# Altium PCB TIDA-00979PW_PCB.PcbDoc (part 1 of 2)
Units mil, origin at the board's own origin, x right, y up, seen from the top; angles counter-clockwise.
Board outline 2100 x 2800 mil, 4 copper layers (Top Layer, L02 - GND, L03 - SUPPLY, Bottom Layer), stack 61.17 mil thick; 75 components, 60 nets, 300 pads, 112 vias.
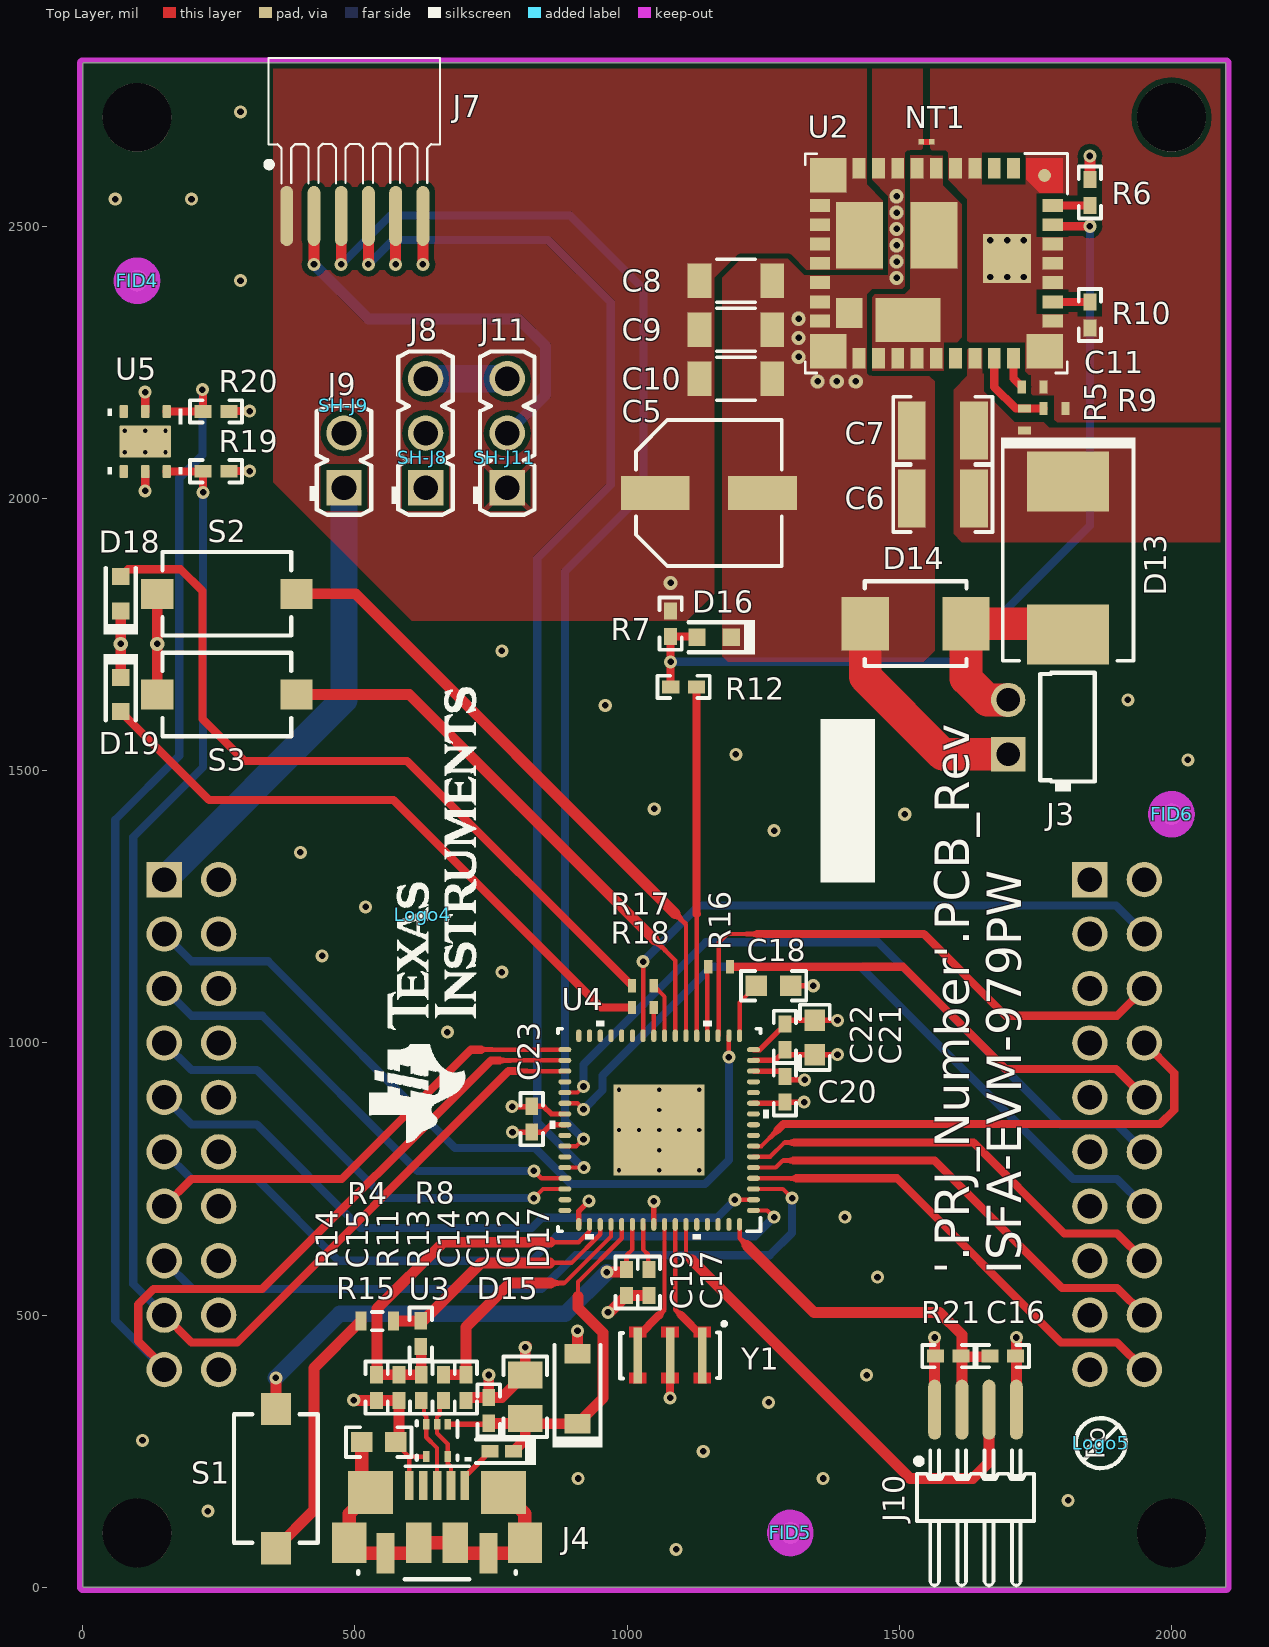
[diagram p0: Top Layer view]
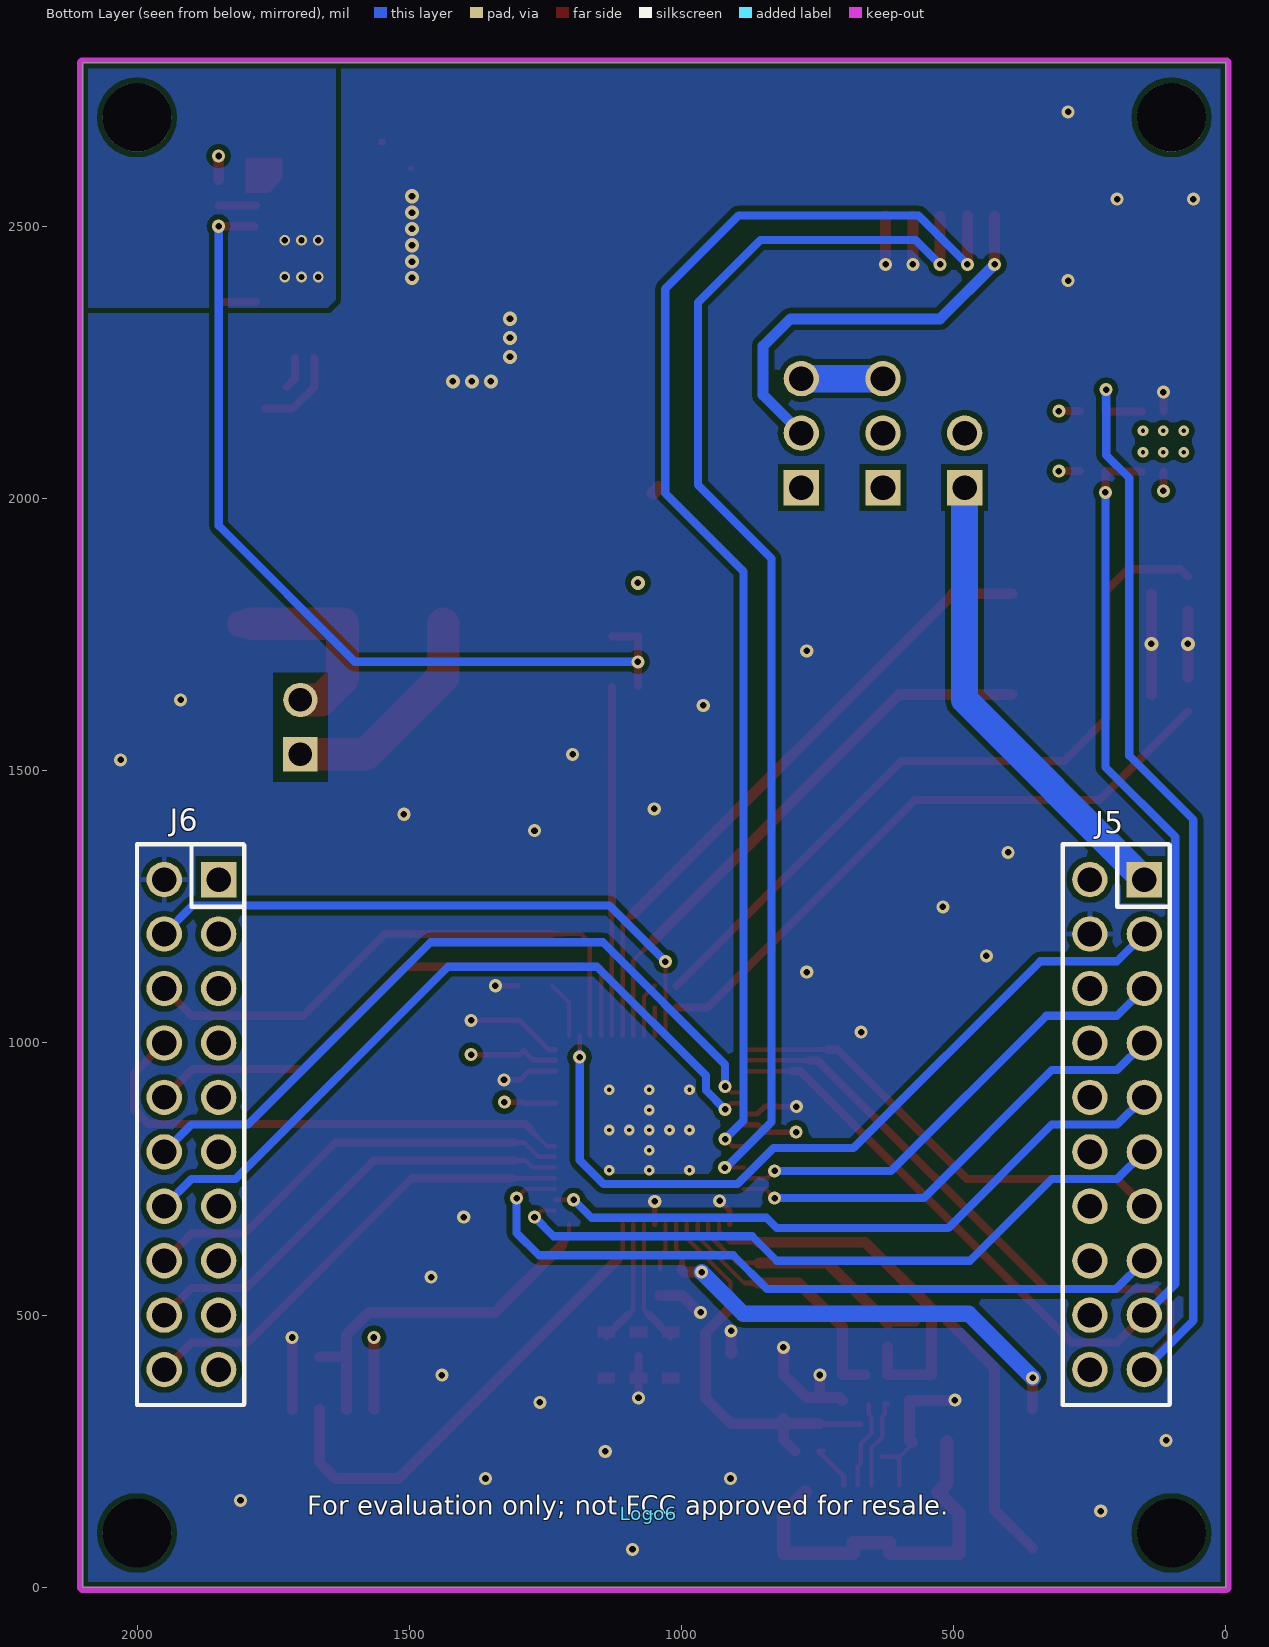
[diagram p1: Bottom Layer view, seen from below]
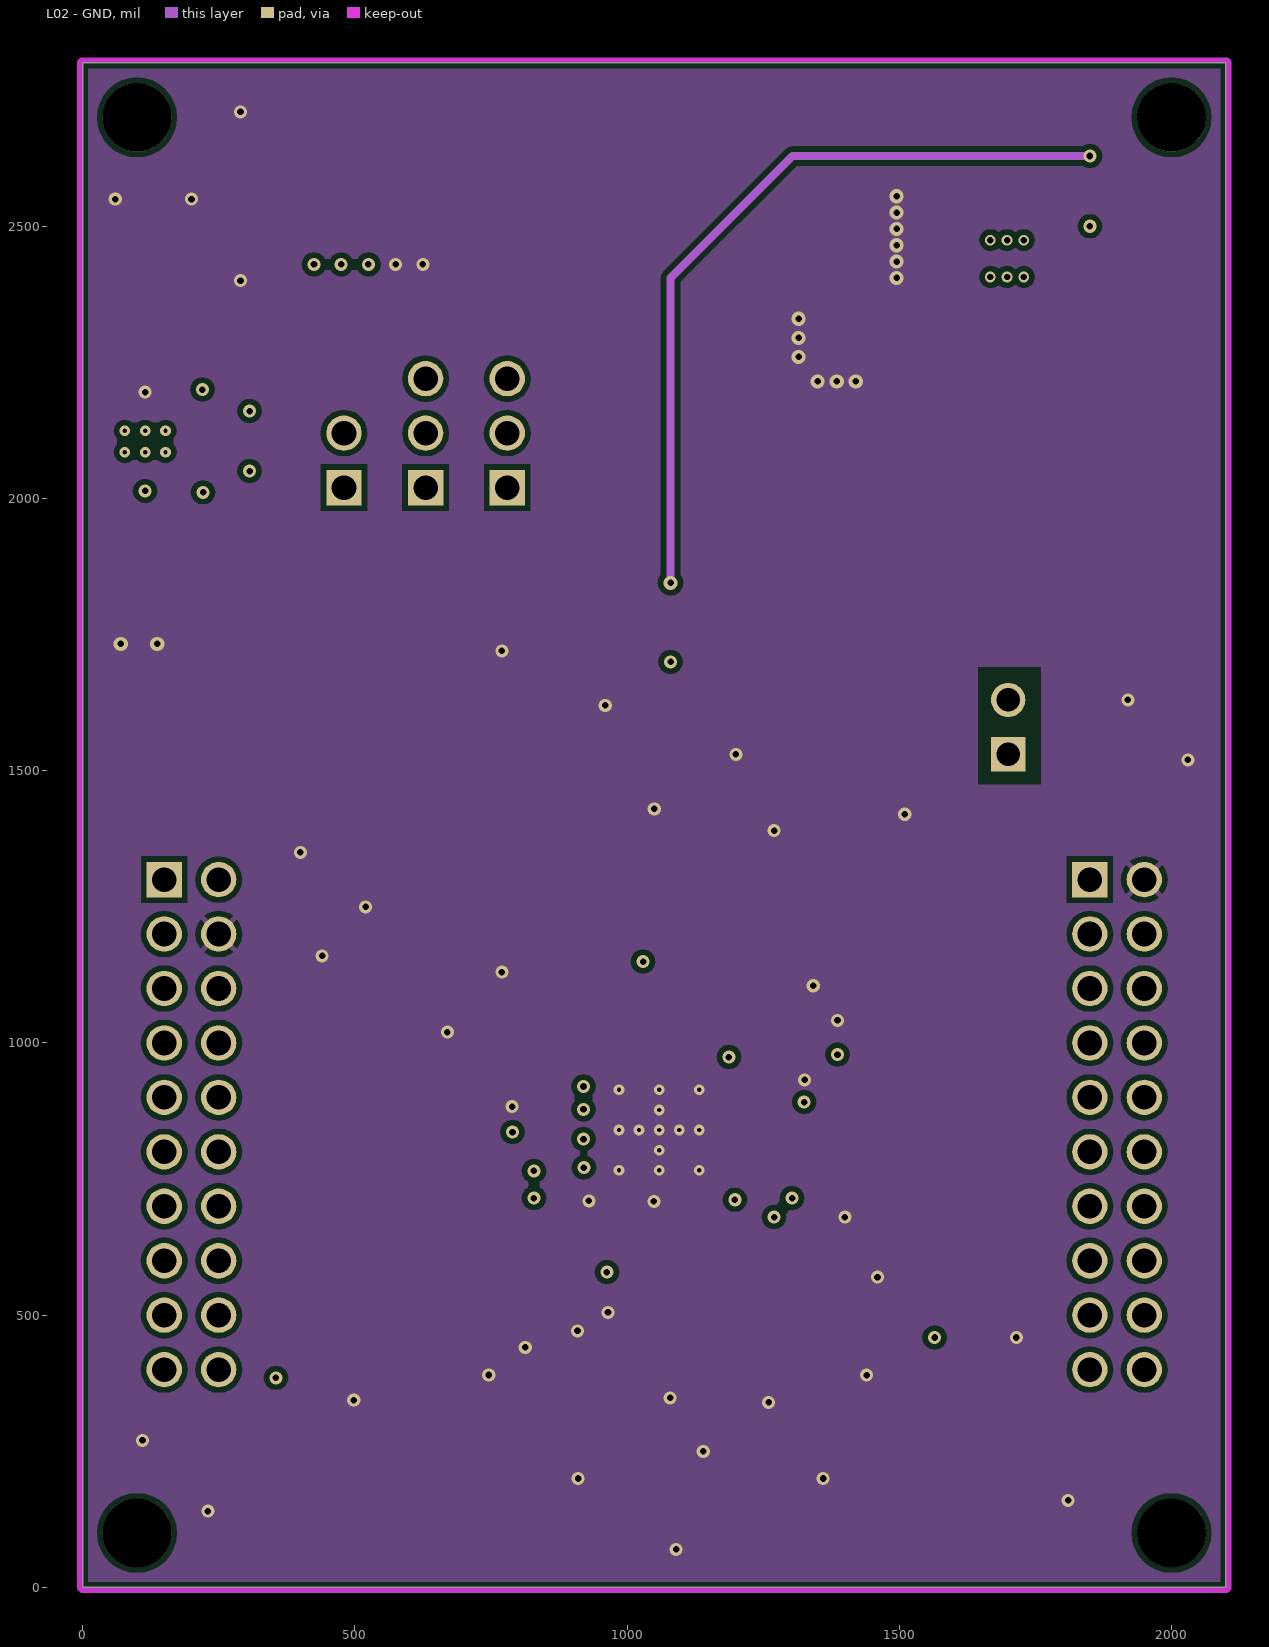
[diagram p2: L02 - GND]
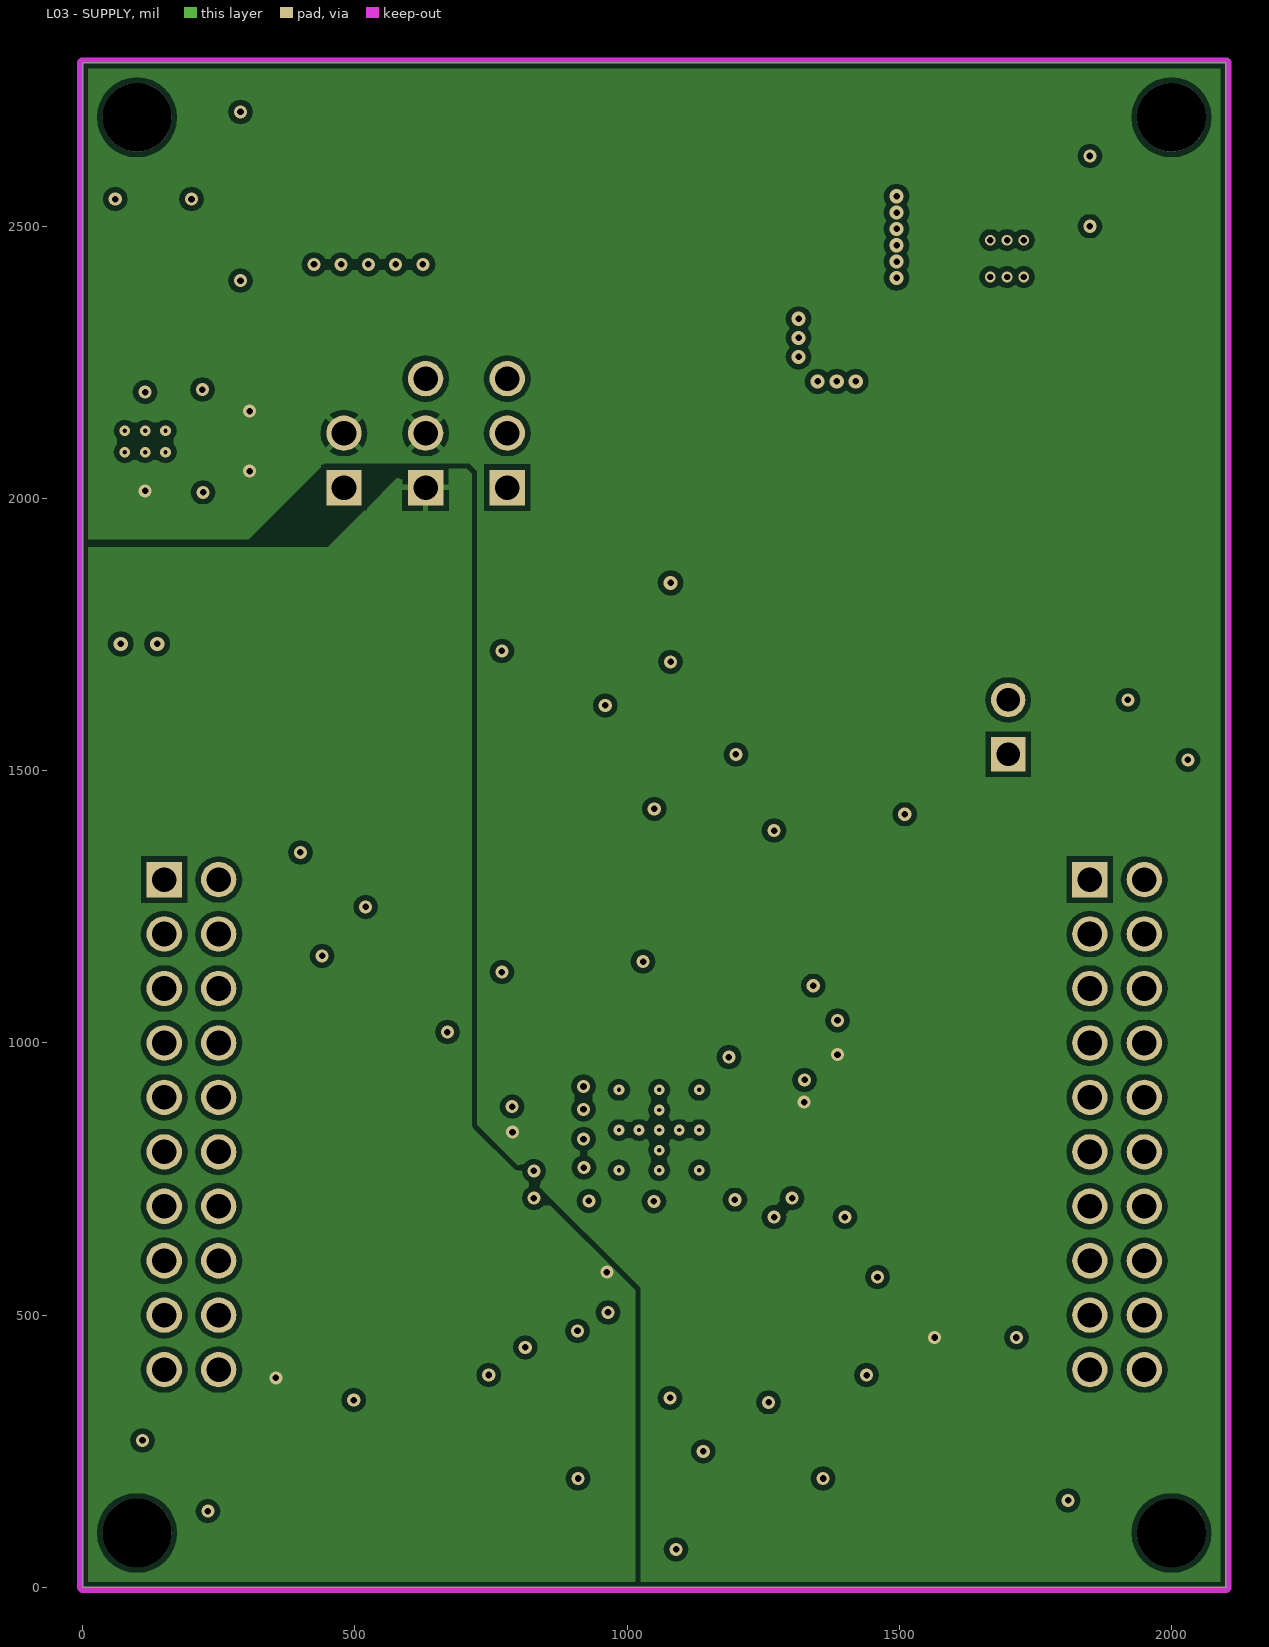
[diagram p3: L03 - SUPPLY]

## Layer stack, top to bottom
Top Solder: solder mask 0.4, Solder Resist, Dk 3.5
Top Layer: signal copper 1.4
Dielectric1: core 10, FR-4, Dk 4.8
L02 - GND: signal copper 1.4
Dielectric 3: prepreg 35.57, FR-4, Dk 4.8
L03 - SUPPLY: signal copper 1.4
Dielectric 2: core 10, FR-4, Dk 4.8
Bottom Layer: signal copper 1.4
Bottom Solder: solder mask 0.4, Solder Resist, Dk 3.5

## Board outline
0,0 2100,0 2100,2800 0,2800

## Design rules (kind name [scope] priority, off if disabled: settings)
AcuteAngle [All] p1: minimum=4.50000000000000E+0001 checktracksonly=FALSE
AssemblyTestPointUsage [All] p1: valid=2
Clearance Clearance_Region_NT1 [All vs InComponent('NT1')] p1: gap=7.87 except(0: Poly-Region)
Clearance Clearance_Keepouts [((IsTrack Or IsArc) And Not InPoly) And IsFree and IsKeepOut vs ((IsTrack Or IsArc) And Not InPoly) And IsFree and IsKeepOut] p2: gap=0
Clearance Clearance_Poly [InPolygon] p3: gap=10
Clearance [All] p4: gap=7.87
ComponentClearance ComponentClearance_MountingHoles_FiducialMarks [InComponentClass('Mounting Holes') vs InComponentClass('FiducialMark')] p1: gap=50 collisioncheckmode=3 verticalgap=10 showdistances=FALSE
ComponentClearance ComponentClearance_Shunt [InComponentClass('Header') vs HasFootprint('Wurth_60900213421')] p2: gap=0 collisioncheckmode=3 verticalgap=0 showdistances=FALSE
ComponentClearance ComponentClearance_Logo [InComponentClass('Logo')] p3: gap=50 collisioncheckmode=3 verticalgap=10 showdistances=FALSE
ComponentClearance ComponentClearance_ScrewToNut [(HasFootprint('NY PMS 440 0025 PH')) vs (HasFootprint('Keystone_1902C'))] p4: gap=5 collisioncheckmode=3 verticalgap=10 showdistances=FALSE
ComponentClearance ComponentClearance_MountingHoles [InComponentClass('Mounting Holes')] p5: gap=250 collisioncheckmode=3 verticalgap=100000 showdistances=FALSE
ComponentClearance ComponentClearance_SmallPassives [HasFootprint('0201*') or HasFootprint('0402*') or HasFootprint('0508') or HasFootprint('0603*') or HasFootprint('0612') or HasFootprint('0805*') or HasFootprint('0815*') or HasFootprint('0830*') or HasFootprint('1206*') or HasFootprint('1210*') or HasFootprint('1808*') or HasFootprint('1812*') or HasFootprint('1825*') or HasFootprint('2010*') or HasFootprint('2220*') or HasFootprint('2225*') or HasFootprint('2512*') or HasFootprint('2728*') or HasFootprint('3518*') vs HasFootprint('0201*') or HasFootprint('0402*') or HasFootprint('0508') or HasFootprint('0603*') or HasFootprint('0612') or HasFootprint('0805*') or HasFootprint('0815*') or HasFootprint('0830*') or HasFootprint('1206*') or HasFootprint('1210*') or HasFootprint('1808*') or HasFootprint('1812*') or HasFootprint('1825*') or HasFootprint('2010*') or HasFootprint('2220*') or HasFootprint('2225*') or HasFootprint('2512*') or HasFootprint('2728*') or HasFootprint('3518*')] p6: gap=14.96 collisioncheckmode=3 verticalgap=10 showdistances=FALSE
ComponentClearance ComponentClearance_THtoSMT [IsThruComponent vs IsSMTComponent] p7: gap=40 collisioncheckmode=3 verticalgap=30 showdistances=FALSE
ComponentClearance ComponentClearance_THtoTH [IsThruComponent vs IsThruComponent] p8: gap=30 collisioncheckmode=3 verticalgap=30 showdistances=FALSE
ComponentClearance [All] p9: gap=30 collisioncheckmode=3 verticalgap=10 showdistances=FALSE
ComponentClearance ComponentClearance_SHUNT2 [HasFootprint('Wurth_60900213421')] p10: gap=30 collisioncheckmode=3 verticalgap=10 showdistances=TRUE
DiffPairsRouting [All] p1: maxlimit=100 minlimit=10 mostfreqgap=10 toplayer_minwidth=15 toplayer_maxwidth=15 toplayer_prefwidth=15 midlayer1_minwidth=15 midlayer1_maxwidth=15 midlayer1_prefwidth=15 midlayer2_minwidth=15 midlayer2_maxwidth=15 midlayer2_prefwidth=15 bottomlayer_minwidth=15 bottomlayer_maxwidth=15 bottomlayer_prefwidth=15 maxuncoupledlength=1000
FabricationTestPointUsage TestPointUsage [All] p1: valid=2 allowmultiple=FALSE
FabricationTestpoint Testpoint [All] p1: side=3 testpointundercomponent=TRUE minsize=40 maxsize=100 preferedsize=60 minholesize=0 maxholesize=40 preferedholesize=32 testpointgrid=1 allowsidetop=TRUE allowsidebottom=TRUE usegrid=TRUE gridtolerance=0.01
FanoutControl Fanout_LCC [IsLCC] p1: bgadir=Out bgaviamode=Centered fanoutstyle=Auto fanoutdirection=Alternating viagrid=1 // Fanout_LCC (Default Rule)
FanoutControl Fanout_BGA [IsBGA] p2: bgadir=Out bgaviamode=Centered fanoutstyle=Auto fanoutdirection=Alternating viagrid=1 // Fanout_BGA (Default Rule)
FanoutControl Fanout_Default [All] p4: bgadir=Out bgaviamode=Centered fanoutstyle=Auto fanoutdirection=Alternating viagrid=1 // Fanout_Default (Default Rule)
FanoutControl Fanout_Small [(CompPinCount < 5)] p5: bgadir=Out bgaviamode=Centered fanoutstyle=Auto fanoutdirection=OutThenIn viagrid=1 // Fanout_Small (Default Rule)
HoleSize [All] p1: absolutevalues=TRUE maxlimit=251 minlimit=7.87 maxpercent=80.000 minpercent=20.000
MinimumAnnularRing MinimumAnnularRing_ThermalPadVias [IsVia and InAnyComponent] p1: minimumring=3.94
MinimumAnnularRing [All] p2: minimumring=6
MinimumSolderMaskSliver MinimumSolderMaskSliver_Logo [InComponentClass('Logo') vs InComponentClass('Logo')] p1: minsoldermaskwidth=0.7
MinimumSolderMaskSliver [All] p2: minsoldermaskwidth=3.94
PlaneConnect [All] p1: planeconnectstyle=Direct reliefexpansion=10 reliefentries=4 reliefconductorwidth=10 reliefairgap=10
PolygonConnect PolygonConnect_9 [IsThruPin vs IsNamedPolygon('GND_L04_P018')] p1: connectstyle=Relief reliefconductorwidth=10 reliefentries=4 polygonreliefangle="90 Angle" airgapwidth=10
PolygonConnect PolygonConnect_8 [IsThruPin vs IsNamedPolygon('+3V3_L03_P012')] p2: connectstyle=Relief reliefconductorwidth=10 reliefentries=4 polygonreliefangle="45 Angle" airgapwidth=10
PolygonConnect PolygonConnect_7 [IsThruPin vs IsNamedPolygon('VUSB_L03_P014')] p3: connectstyle=Relief reliefconductorwidth=10 reliefentries=4 polygonreliefangle="90 Angle" airgapwidth=10
PolygonConnect PolygonConnect_6 [IsThruPin vs IsNamedPolygon('GND_L02_P010')] p4: connectstyle=Relief reliefconductorwidth=10 reliefentries=4 polygonreliefangle="45 Angle" airgapwidth=10
PolygonConnect PolygonConnect_5 [IsThruPin vs IsNamedPolygon('VLED_L01_P008')] p5: connectstyle=Relief reliefconductorwidth=10 reliefentries=4 polygonreliefangle="45 Angle" airgapwidth=10
PolygonConnect PolygonConnect_4 [IsThruPin vs IsNamedPolygon('GND_L01_P006')] p6: connectstyle=Relief reliefconductorwidth=10 reliefentries=4 polygonreliefangle="45 Angle" airgapwidth=10
PolygonConnect PolygonConnect_3 [IsThruPin vs IsNamedPolygon('NETC6_1_L01_P004')] p7: connectstyle=Relief reliefconductorwidth=10 reliefentries=4 polygonreliefangle="45 Angle" airgapwidth=10
PolygonConnect PolygonConnect_2 [IsThruPin vs IsNamedPolygon('NETU2_6_L01_P002')] p8: connectstyle=Relief reliefconductorwidth=10 reliefentries=4 polygonreliefangle="45 Angle" airgapwidth=10
PolygonConnect PolygonConnect_1 [IsThruPin vs IsNamedPolygon('AGND_L01_P000')] p9: connectstyle=Relief reliefconductorwidth=10 reliefentries=4 polygonreliefangle="45 Angle" airgapwidth=10
PolygonConnect [All] p10: connectstyle=Direct reliefconductorwidth=10 reliefentries=4 polygonreliefangle="90 Angle" airgapwidth=10
RoutingVias ThermalPadVias [IsVia and InAnyComponent] p1: holewidth=7.87 width=19.68 viastyle="Through Hole" minholewidth=7.87 minwidth=19.68 maxholewidth=12.99 maxwidth=23.62
RoutingVias [All] p2: holewidth=12 width=26 viastyle="Through Hole" minholewidth=7.87 minwidth=19 maxholewidth=40 maxwidth=65
ShortCircuit ShortCircuit_HDC1080 [HasFootprintPad('DMB0006A','7') vs IsVia] p1: allowed=TRUE
ShortCircuit [All] p2: allowed=FALSE
SilkToBoardRegionClearance [Not ((IsComment or IsDesignator) And (Hide <> 'False')) and not InRegion(1000,500,4000,800)] p1:
SilkToSilkClearance SilkToSilkClearance_Pb-FreeLogo [(HasFootprint('Pb-Free_Overlay_Medium') OR HasFootprint('Pb-Free_Overlay_Small')) vs (HasFootprint('Pb-Free_Overlay_Medium') OR HasFootprint('Pb-Free_Overlay_Small'))] p1: silktosilkclearance=0
SilkToSilkClearance [All] p2: silktosilkclearance=4
SilkToSolderMaskClearance SilkToComponentPadClearance [IsPad and InAnycomponent] p1: minsilkscreentomaskgap=5 clearancetoexposedcopper=TRUE
SilkToSolderMaskClearance "Silk to Solder Mask Opening" [All] p2: minsilkscreentomaskgap=4 clearancetoexposedcopper=FALSE
SolderMaskExpansion [All] p1: expansion=1.97
Width [All] p1: maxlimit=100 minlimit=6 preferedwidth=15 checkconnectedcopper=TRUE
14 further rules are at their usual default settings.

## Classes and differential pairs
component class Header: J3 J8 J9 J11
component class AssemblyNote: ZZ5 ZZ6 ZZ7
component class FiducialMark: FID4 FID5 FID6
component class TIDA-00979PW_CoverSheet: FID4 FID5 FID6 Logo4 Logo5 Logo6 ZZ4 ZZ5 ZZ6 ZZ7
component class Logo: Logo4
component class TIDA-00979PW_Control: C5 C6 C7 C8 C9 C10 C11 C12 C13 C14 C15 C16 C17 C18 C19 C20 C21 C22 C23 D1 D13 D14 D15 D16 D17 D18 D19 J3 J4 J5 J6 J7 J8 J9 J10 J11 J? NT1 R4 R5 R6 R7 R8 R9 R10 R11 R12 R13 R14 R15 R16 R17 R18 R19 R20 R21 S1 S2 S3 SH-J8 SH-J9 SH-J11 U2 U3 U4 U5 Y1

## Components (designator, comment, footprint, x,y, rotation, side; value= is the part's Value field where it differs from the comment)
C5 "EEE-FK1E680P" SM_RADIAL_D 1150.32,2010 r0 top
C6 "C3225X7S2A335M200AB" 1210 1580,2000 r180 top
C7 "C3225X7S2A335M200AB" 1210 1580,2125 r180 top
C8 "C3216X5R1E476M160AC" 1206_190 1200,2400 r0 top
C9 "C3216X5R1E476M160AC" 1206_190 1200,2310 r0 top
C10 "C3216X5R1E476M160AC" 1206_190 1200,2220 r0 top
C11 "C1005X7R1E223K" 0402S 1745,2205 r0 top
C12 "GRM21BR71C475KA73L" 0805_HV 813,350 r90 top
C13 "C1005X7R1H104K050BB" 0402 746,325 r90 top
C14 "500R07S100JV4T" 0402 704,367 r270 top
C15 "500R07S100JV4T" 0402 581,367 r270 top
C16 "885012205008" 0402 1690,425 r0 top
C17 "C1005X7R1C224K050BC" 0402 1040,560 r270 top
C18 "C0603C474K8RACTU" 0603 1269,1105 r0 top
C19 "C1005X7R1C224K050BC" 0402 999,560 r270 top
C20 "C1005X7R1H104K050BB" 0402 1290,915 r90 top
C21 "C1608X5R1A106M080AC" 0603 1345,1010 r90 top
C22 "C1005X7R1H104K050BB" 0402 1290,1011 r90 top
C23 "C1005X7R1H104K050BB" 0402 825,860 r90 top
D13 "ES3D-E3/57T" SMC 1810,1891 r270 top
D14 "SM6T39CA" SMB-Bi 1530,1770 r0 top
D15 "SBR0220T5-7-F" SOD-523 770,250 r180 top
D16 "150060GS75000" WL-SMCW_GREEN 1160,1745 r180 top
D17 "MMSZ5232B-7-F" SOD-123 909,365 r90 top
D18 "150060GS75000" WL-SMCW_GREEN 70,1825 r90 top
D19 "150060GS75000" WL-SMCW_GREEN 70,1640 r270 top
FID4 "Fiducial" Fiducial10-20 100,2400 r0 top
FID5 "Fiducial" Fiducial10-20 1300,100 r0 top
FID6 "Fiducial" Fiducial10-20 2000,1420 r0 top
J3 "61300211021" Wurth_61300211021 1700,1580 r90 top
J4 "ZX62R-B-5P" Hirose_ZX62R-B-5P 651,82 r270 top
J5 "SSW-110-23-F-D" CONN_SSW-110-23-F-D 200,850 r90 bottom locked
J6 "SSW-110-23-F-D" CONN_SSW-110-23-F-D 1900,850 r90 bottom locked
J7 "851-11-006-40-001000" Mill-Max_851-11-006-40-001000 500,2700 r90 top
J8 "61300311121" WURTH_61300311121 630,2120 r90 top
J9 "61300211121" WURTH_61300211121 480,2070 r90 top
J10 "850-10-004-40-001000" Mill-max_850-10-004-40-001000 1640,165 r0 top
J11 "61300311121" WURTH_61300311121 780,2120 r90 top
Logo4 "Texas Instruments" TI_Stacked_Overlay_Small 625,1235 r90 top
Logo5 "Pb-Free Symbol" Pb-Free_Overlay_Small 1870,265 r90 top
Logo6 "FCC disclaimer" FCC_disclaimer 1060,135 r180 bottom
NT1 "Net-Tie" Net-Tie_10mil 1550,2655 r180 top net-tie
R4 "CRCW0603100RFKEA" 0603S 541,489 r0 top
R5 "CRCW0402174KFKED" 0402S 1730,2145 r270 top
R6 "CRCW0402140KFKED" 0402 1850,2562 r90 top
R7 "CRCW04026K81FKED" 0402 1080,1770 r90 top
R8 "ERJ-2RKF1401X" 0402 621,466 r90 top
R9 "CRCW040215K8FKED" 0402S 1785,2165 r180 top
R10 "CRCW0402267KFKED" 0402 1850,2337 r90 top
R11 "CRCW040227R0JNED" 0402 622,367 r90 top
R12 "CRCW04020000Z0ED" 0402 1104,1654 r0 top
R13 "CRCW040227R0JNED" 0402 663,367 r90 top
R14 "CRCW04021M00JNED" 0402 540,367 r90 top
R15 "CRCW060333R0FKEA" 0603 544,267 r180 top
R16 "CRCW04020000Z0ED" 0402S 1169,1140 r180 top
R17 "CRCW04021K02FKED" 0402S 1029,1105 r180 top
R18 "CRCW04021K02FKED" 0402S 1029,1065 r180 top
R19 "CRCW04024K99FKED" 0402 245,2050 r0 top
R20 "CRCW04024K99FKED" 0402 245,2160 r0 top
R21 "CRCW040247K5FKED" 0402 1590,425 r180 top
S1 "434121025816" SW_434121025816 355,200 r90 top
S2 "434121025816" SW_434121025816 265,1824.99 r0 top
S3 "434121025816" SW_434121025816 265,1639.99 r0 top
SH-J8 "60900213421" Wurth_60900213421 625,2075 r90 top
SH-J9 "60900213421" Wurth_60900213421 479.99,2170.01 r90 top
SH-J11 "60900213421" Wurth_60900213421 775,2075 r90 top
U2 "LMZ35003RKGR" RKG0041A 1568,2432 r270 top
U3 "TPD2E001DRLR" DRL0005A 651,270 r270 top
U4 "MSP430F5528IRGCR" RGC0064B 1059,840 r180 top
U5 "HDC1080DMBR" DMB0006A 115,2104.68 r270 top
Y1 "CSTCR4M00G15L99-R0" Murata_CSTCR 1079,426 r180 top
ZZ4 "Place: SH-J8 to J8-PINs 1-2; SH-J9 to J9-PIN 1 (NO SHORT); SH-J11 to J11-PINs 1-2" AssemblyNote 200,3400 r0 top
ZZ5 "These assemblies are ESD sensitive, ESD precautions shall be observed." AssemblyNote 200,3300 r0 top
ZZ6 "These assemblies must be clean and free from flux and all contaminants. Use of no clean flux is not acceptable." AssemblyNote 200,3200 r0 top
ZZ7 "These assemblies must comply with workmanship standards IPC-A-610 Class 2, unless otherwise specified." AssemblyNote 200,3100 r0 top

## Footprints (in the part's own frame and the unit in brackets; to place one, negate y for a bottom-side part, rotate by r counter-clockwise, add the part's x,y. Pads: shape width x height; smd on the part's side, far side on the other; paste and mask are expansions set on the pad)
0402 [mm] "0402 from SM-752 data"
  rect 0.8x0.6 smd: 1(-0.6,0) 2(0.6,0)
  silkscreen extent -1.22,-0.52 1.22,0.52, body extent -0.55,-0.3 0.55,0.3, height 0.6
0402S [mil] "Based on C0402S footprint from PADS legacy"
  rect 15x24 smd: 1(-20,0) 2(20,0)
  body extent -22,-12 22,12, height 24
0603 [mm] "0603 from SM-752 data"
  rect 1x0.95 smd: 1(-0.8,0) 2(0.8,0)
  silkscreen extent -1.52,-0.69 1.52,0.69, body extent -0.87,-0.47 0.87,0.47, height 1
0603S [mil]
  rect 20x35 smd: 1(-30,0) 2(30,0)
  silkscreen extent -10,-17 10,17, body extent -34,-19 34,19, height 39
0805_HV [mil] "0805 with 30mil clearance between pads"
  rect 50x63 smd: 1(-40,0) 2(40,0)
  silkscreen extent -74,-40 74,40, body extent -43,-29 43,29, height 57
1206_190 [mm] "1206_190"
  rect 1.1x1.6 smd: 1(-1.7,0) 2(1.7,0)
  silkscreen extent -0.9,-1 0.9,1, body extent -1.75,-0.95 1.75,0.95, height 1.9
1210 [mm] "1210 from SM-752 data"
  rect 1.3x2.7 smd: 1(-1.45,0) 2(1.45,0)
  silkscreen extent -2.32,-1.57 2.32,1.57, body extent -1.7,-1.35 1.7,1.35, height 1.35
AssemblyNote [mil] "Assembly Note"
CONN_SSW-110-23-F-D [mm] "SAMTEC"
  rect 1.65x1.65 hole 1.15: 1(11.43,-1.27)
  round 1.65 hole 1.15: 2(11.43,1.27) 3(8.89,-1.27) 4(8.89,1.27) 5(6.35,-1.27) 6(6.35,1.27) 7(3.81,-1.27) 8(3.81,1.27) 9(1.27,-1.27) 10(1.27,1.27) 11(-1.27,-1.27) 12(-1.27,1.27) 13(-3.81,-1.27) 14(-3.81,1.27) 15(-6.35,-1.27) 16(-6.35,1.27) 17(-8.89,-1.27) 18(-8.89,1.27) 19(-11.43,-1.27) 20(-11.43,1.27)
  silkscreen extent -13.08,-2.46 13.08,2.54, body extent -13,-2.51 13,2.54, height 8.59
DMB0006A [mm] "TI"
  rrect25% 0.6x0.4 smd: 1(-1.4,1) 2(-1.4,0) 3(-1.4,-1) 4(1.4,-1) 5(1.4,0) 6(1.4,1)
  rrect7% 1.5x2.4 smd paste-0.75: 7(0,0)
  silkscreen extent -1.55,-1.75 1.55,1.75, body extent -1.5,-1.5 1.5,1.5, height 0.81
DRL0005A [mm] "SOTFL, 5-Flat Leads, Body 1.2x1.6x0.6mm, Pitch 0.5mm, TI recommended"
  rect 0.5x0.3 smd: 1(-0.75,0.5) 2(-0.75,0) 3(-0.75,-0.5) 4(0.75,-0.5) 5(0.75,0.5)
  silkscreen extent -0.9,-0.95 0.9,0.95, body extent -0.85,-0.85 0.85,0.85, height 0.62
FCC_disclaimer [mil]
Fiducial10-20 [mm]
  round 1 smd mask+0.5: 1(0,0)
  Top Layer keep-out circle w1.178: c0,0 r0.5
Hirose_ZX62R-B-5P [mm] "Hirose"
  rect 1.35x0.4 smd: 1(-2.68,1.3) 2(-2.68,0.65) 3(-2.68,0) 4(-2.68,-0.65) 5(-2.68,-1.3)
  rect 2x2.1 smd: 6(-2.35,-3.1) 7(-2.35,3.1)
  rect 1.9x1.6 smd: 8(0,-4.1) 13(0,4.1)
  rect 1.88x0.85 smd: 9(0.495,-2.4) 12(0.495,2.4)
  rect 1.9x1.2 smd: 10(0,-0.85) 11(0,0.85)
  silkscreen extent -4,-3.67 1.7,3.67, body extent -2.57,-3.48 2.11,3.45, height 2.65
Mill-max_850-10-004-40-001000 [mm] "Mill-max"
  oval 0.6x2.8 smd: 1(-1.905,4.1) 2(-0.635,4.1) 3(0.635,4.1) 4(1.905,4.1)
  silkscreen extent -2.78,-4.1 2.73,2.21, body extent -2.72,-4.08 2.74,5.43, height 2.13
Mill-Max_851-11-006-40-001000 [mm] "Mill-max"
  oval 2.8x0.6 smd: 1(-4.6,3.175) 2(-4.6,1.905) 3(-4.6,0.635) 4(-4.6,-0.635) 5(-4.6,-1.905) 6(-4.6,-3.175)
  silkscreen extent -3.08,-3.98 2.77,4.14, body extent -5.96,-4 2.77,4.01, height 2.03
Murata_CSTCR [mm] "Murata"
  rect 0.4x2.6 smd mask+0.051: 1(-1.5,0) 2(0,0) 3(1.5,0)
  Top Layer region: -0.4,0.8 0.4,0.8 0.4,1.3 -0.4,1.3
  Top Layer region: -0.4,-1.35 -0.4,-0.85 0.4,-0.85 0.4,-1.35
  Top Layer region: -0.4,-1.35 -0.4,-0.85 0.4,-0.85 0.4,-1.35
  Top Layer region: -1.9,0.8 -1.1,0.8 -1.1,1.3 -1.9,1.3
  Top Layer region: -1.9,-1.35 -1.9,-0.85 -1.1,-0.85 -1.1,-1.35
  Top Layer region: -1.9,-1.35 -1.9,-0.85 -1.1,-0.85 -1.1,-1.35
  Top Layer region: 1.1,0.8 1.9,0.8 1.9,1.3 1.1,1.3
  Top Layer region: 1.1,-1.35 1.1,-0.85 1.9,-0.85 1.9,-1.35
  Top Layer region: 1.1,-1.35 1.1,-0.85 1.9,-0.85 1.9,-1.35
  silkscreen extent -2.61,-1.56 2.32,1.08, body extent -2.3,-1.05 2.3,1.05, height 1.2
Net-Tie_10mil [mil] "10mil net tie, no solder mask opening, no solder paste"
  rect 10x10 smd paste-5 mask-5: 1(-10,0) 2(10,0)
  Top Layer region: -6,5 6,5 6,-5 -6,-5
Pb-Free_Overlay_Small [mil]
  silkscreen extent -46,-46 46,46
RGC0064B [mm]
  oval 0.6x0.24 smd mask+0.07: 1(-4.4,3.75) 2(-4.4,3.25) 3(-4.4,2.75) 4(-4.4,2.25) 5(-4.4,1.75) 6(-4.4,1.25) 7(-4.4,0.75) 8(-4.4,0.25) 9(-4.4,-0.25) 10(-4.4,-0.75) 11(-4.4,-1.25) 12(-4.4,-1.75) 13(-4.4,-2.25) 14(-4.4,-2.75) 15(-4.4,-3.25) 16(-4.4,-3.75) 33(4.4,-3.75) 34(4.4,-3.25) 35(4.4,-2.75) 36(4.4,-2.25) 37(4.4,-1.75) 38(4.4,-1.25) 39(4.4,-0.75) 40(4.4,-0.25) 41(4.4,0.25) 42(4.4,0.75) 43(4.4,1.25) 44(4.4,1.75) 45(4.4,2.25) 46(4.4,2.75) 47(4.4,3.25) 48(4.4,3.75)
  oval 0.24x0.6 smd mask+0.07: 17(-3.751,-4.4) 18(-3.251,-4.4) 19(-2.751,-4.4) 20(-2.251,-4.4) 21(-1.75,-4.4) 22(-1.25,-4.4) 23(-0.75,-4.4) 24(-0.25,-4.4) 25(0.25,-4.4) 26(0.75,-4.4) 27(1.25,-4.4) 28(1.75,-4.4) 29(2.251,-4.4) 30(2.751,-4.4) 31(3.251,-4.4) 32(3.751,-4.4) 49(3.751,4.4) 50(3.251,4.4) 51(2.751,4.4) 52(2.251,4.4) 53(1.75,4.4) 54(1.25,4.4) 55(0.75,4.4) 56(0.25,4.4) 57(-0.25,4.4) 58(-0.75,4.4) 59(-1.25,4.4) 60(-1.75,4.4) 61(-2.251,4.4) 62(-2.751,4.4) 63(-3.251,4.4) 64(-3.751,4.4)
  rect 4.25x4.25 smd paste-2.112: 65(0,0)
  silkscreen extent -5.1,-5.1 5.1,5.1, body extent -4.57,-4.57 4.57,4.57, height 1.01
RKG0041A [mm] "QFN-41, 9X11mm"
  round 0.6 smd: 1(-4.1,5.05)
  rect 0.95x0.6 smd paste-0.025: 2(-4.425,3.6) 3(-4.425,2.7) 4(-4.425,1.8) 5(-4.425,0.9) 6(-4.425,0) 7(-4.425,-0.9) 8(-4.425,-1.8) 9(-4.425,-2.7) 10(-4.425,-3.6) 20(4.425,-3.6) 21(4.425,-2.7) 22(4.425,-1.8) 23(4.425,-0.9) 24(4.425,0) 25(4.425,0.9) 26(4.425,1.8) 27(4.425,2.7) 28(4.425,3.6)
  rect 1.6x1.7 smd paste-0.8: 11(-4.1,-5.05) 19(4.1,-5.05) 29(4.1,5.05)
  rect 0.6x0.95 smd paste-0.025: 12(-2.7,-5.425) 13(-1.8,-5.425) 14(-0.9,-5.425) 15(0,-5.425) 16(0.9,-5.425) 17(1.8,-5.425) 18(2.7,-5.425) 30(2.7,5.425) 31(1.8,5.425) 32(0.9,5.425) 33(0,5.425) 34(-0.9,5.425) 35(-1.8,5.425) 36(-2.7,5.425)
  rect 2.3x2.25 smd paste-1.2 mask-1.15: 37(-0.22,3.3)
  rect 3.1x2.2 smd paste-1.1: 38(-1.3,-0.11) 39(-1.3,-3.59)
  rect 1.4x1.24 smd paste-0.7: 40(2.33,-4.06)
  rect 2.04x3.05 smd paste-1.02: 41(2.65,-1.32)
  Top Layer region: -4.9,5.9 -4.9,4.2 -3.913,4.2 -3.3,4.815 -3.3,5.9 -4.9,5.9
  silkscreen extent -5.13,-6.11 5.12,6.12, body extent -4.57,-5.57 4.57,5.57, height 2.91
SM_RADIAL_D [mm] "6.3 x 5.8mm:  Panasonic D"
  rect 3.2x1.6 smd: 1(-2.5,0) 2(2.5,0)
  silkscreen extent -3.4,-3.4 3.4,3.4, body extent -3.4,-3.4 3.4,3.4, height 6.1
SMB-Bi [mm] "Fairchild recommended land pattern"
  rect 2.2x2.5 smd: 1(-2.35,0) 2(2.35,0)
  silkscreen extent -2.37,-1.97 2.37,1.97, body extent -2.37,-1.97 2.37,1.97, height 2.65
SMC [mil] "Molded Diode, 2-Leads, Body 6.9x5.8mm, IPC Medium Density, based on OnSemi component dimensions and land patterns"
  rect 110x150 smd: 1(-140.49,0) 2(140.49,0)
  silkscreen extent -221,-124 189,123, body extent -156,-116 156,116, height 91
SOD-123 [mm] "On Semi recommended land pattern"
  rect 0.915x1.22 smd: 1(-1.637,0) 2(1.637,0)
  silkscreen extent -2.74,-1.17 2.03,1.17, body extent -1.93,-0.9 1.93,0.9, height 1.35
SOD-523 [mm] "NXP Semiconductor recommended land pattern, nominal STEP model"
  rect 0.8x0.6 smd paste-0.05: 1(-0.55,0) 2(0.55,0)
  silkscreen extent -1.6,-0.64 1.2,0.63, body extent -0.8,-0.4 0.8,0.4, height 0.72
SW_434121025816 [mm] "SMD, 2-Leads, Body 6x3.9mm, Pitch 6.5mm"
  rect 1.5x1.4 smd: 1(-3.25,0) 2(3.25,0)
  silkscreen extent -3,-1.95 3,1.95, body extent -3.65,-1.95 3.65,1.95, height 2.5
TI_Stacked_Overlay_Small [mil]
  silkscreen extent -418,-98 418,98
WL-SMCW_GREEN [mm] "WURTH"
  rect 0.8x0.8 smd: 1(-0.8,0) 2(0.8,0)
  silkscreen extent -1.9,-0.8 1.2,0.8, body extent -0.85,-0.45 0.85,0.45, height 0.8
Wurth_60900213421 [mil] "Shunt, 2.54mm, Black"
  round 1 on Mech3: 0(0,0)
  body extent -98,-48 98,48, height 236
Wurth_61300211021 [mm] "Header, 2.54 mm, 2x1, R/A, TH"
  rect 1.6x1.6 hole 1.1: 1(-1.27,0)
  round 1.6 hole 1.1: 2(1.27,0)
  silkscreen extent -3,-4.04 2.54,-1.5, body extent -2.54,-10.04 2.54,0.32, height 2.55
WURTH_61300211121 [mm] "Header, 2.54mm, 2x1, TH"
  rect 1.65x1.65 hole 1.15: 1(-1.27,0)
  round 1.65 hole 1.15: 2(1.27,0)
  silkscreen extent -2.54,-1.27 2.54,1.6, body extent -2.54,-1.27 2.54,1.27, height 8.54
WURTH_61300311121 [mm] "Header, 2.54mm, 3x1, TH"
  rect 1.65x1.65 hole 1.15: 1(-2.54,0)
  round 1.65 hole 1.15: 2(0,0) 3(2.54,0)
  silkscreen extent -3.81,-1.27 3.81,1.6, body extent -3.81,-1.27 3.81,1.27, height 8.54

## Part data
C5: "CAP, AL, 68 µF, 25 V, +/- 20%, 0.36 ohm, SMD"
C6 C7: "CAP, CERM, 3.3 µF, 100 V, +/- 20%, X7S, 1210"
C8 C9 C10: "CAP, CERM, 47 µF, 25 V, +/- 20%, X5R, 1206_190"
C11: "CAP, CERM, 0.022 µF, 25 V, +/- 10%, X7R, 0402"
C12: "CAP, CERM, 4.7 µF, 16 V, +/- 10%, X7R, 0805"
C13 C20 C22 C23: "CAP, CERM, 0.1 µF, 50 V, +/- 10%, X7R, 0402"
C14 C15: "CAP, CERM, 10 pF, 50 V, +/- 5%, C0G/NP0, 0402"
C16: "CAP, CERM, 2200 pF, 10 V, +/- 10%, X7R, 0402"
C17 C19: "CAP, CERM, 0.22 µF, 16 V, +/- 10%, X7R, 0402"
C18: "CAP, CERM, 0.47 µF, 10 V, +/- 10%, X7R, 0603"
C21: "CAP, CERM, 10 µF, 10 V, +/- 20%, X5R, 0603"
D13: "Diode, Ultrafast, 200 V, 3 A, SMC"
D14: "Diode, TVS, Bi, 39 V, 600 W, SMB"
D15: "Diode, Schottky, 20 V, 0.2 A, SOD-523"
D16 D18 D19: "LED, Green, SMD"
D17: "Diode, Zener, 5.6 V, 500 mW, SOD-123"
FID4 FID5 FID6: "Fiducial mark.  There is nothing to buy or mount."
J3: "Header, 2.54 mm, 2x1, Gold, R/A, TH"
J4: "Connector, Receptacle, Micro-USB Type B, SMT"
J5 J6: "Connector, Receptacle, 100mil, 10x2, Gold plated, TH"
J7: "Receptacle, 50mil, 5x1, Gold, R/A, SMT"
J8 J11: "Header, 2.54 mm, 3x1, Gold, TH"
J9: "Header, 2.54 mm, 2x1, Gold, TH"
J10: "Header, 50mil, 4x1, Gold, R/A, SMT"
Logo4: library part TI_Logo, "Texas Instrument Corporate Signature"
Logo5: library part Pb-Free
Logo6: library part FCC_disclaimer, "FCC_disclaimer"
NT1: "Single point connection between nets."
R4: "RES, 100, 1%, 0.1 W, 0603"
R5: "RES, 174 k, 1%, 0.063 W, 0402"
R6: "RES, 140 k, 1%, 0.063 W, 0402"
R7: "RES, 6.81 k, 1%, 0.063 W, 0402"
R8: "RES, 1.40 k, 1%, 0.1 W, 0402"
R9: "RES, 15.8 k, 1%, 0.063 W, 0402"
R10: "RES, 267 k, 1%, 0.063 W, 0402"
R11 R13: "RES, 27, 5%, 0.063 W, 0402"
R12 R16: "RES, 0, 5%, 0.063 W, 0402"
R14: "RES, 1.0 M, 5%, 0.063 W, 0402"
R15: "RES, 33.0, 1%, 0.1 W, 0603"
R17 R18: "RES, 1.02 k, 1%, 0.063 W, 0402"
R19 R20: "RES, 4.99 k, 1%, 0.063 W, 0402"
R21: "RES, 47.5 k, 1%, 0.063 W, 0402"
S1 S2 S3: "Switch, Tactile, SPST, 12 V, SMD"
SH-J8 SH-J9 SH-J11: "Shunt, 2.54mm, Gold, Black"
U2: "7-V to 50-V Input, 2.5-A Step-Down, Integrated Power Solution, RKG0041A"
U3: "Low-Capacitance + / - 15 kV ESD-Protection Array for High-Speed Data Interfaces, 2 Channels, -40 to +85 degC, 5-pin SOT (DRL), Green (RoHS & no Sb/Br)"
U4: "25 MHz Mixed Signal Microcontroller with 128 KB Flash, 8192 B SRAM and 47 GPIOs, -40 to 85 degC, 64-pin QFN (RGC), Green (RoHS & no Sb/Br)"
U5: "Low Power, High Accuracy Digital Humidity Sensor with Temperature Sensor, DMB0006A"
Y1: "Resonator, 4MHz, 39pF SMD"
ZZ4: library part "Assembly Note"
ZZ5 ZZ6 ZZ7: library part AssemblyNote

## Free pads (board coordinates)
  round 125.98 hole 125.98 unplated: 0(100,100) 0(100,2700) 0(2000,100) 0(2000,2700)

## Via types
v1: diameter 24, hole 12, Top Layer to Bottom Layer, tented both sides, 72 vias
v2: diameter 19.68, hole 7.87, Top Layer to Bottom Layer, 19 vias
v3: diameter 26, hole 12, Top Layer to Bottom Layer, tented both sides, 15 vias
v4: diameter 19.68, hole 11.81, Top Layer to Bottom Layer, tented both sides, 6 vias

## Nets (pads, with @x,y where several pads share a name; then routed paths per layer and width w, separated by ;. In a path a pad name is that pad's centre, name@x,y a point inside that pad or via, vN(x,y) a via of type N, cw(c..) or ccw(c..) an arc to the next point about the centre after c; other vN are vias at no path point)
+3V3: C20.1 C21.1 C22.1 C23.1 J8.2 J9.2 J10.1 R19.2 R20.2 R21.2 U4.11 U4.15 U4.40 U5.5 | length 606.3
  Top Layer w10: v1(789.62,836.38) C23.1@825,836.38 846.88,836.38 860.34,849.84 U4.40@885.77,849.84 ; U4.11@1232.23,889.21 1287.83,889.21 C20.1@1290,891.38 v1(1325.38,891.38) ; U4.15@1232.23,967.95 1271.57,967.95 1290,986.38 1297.87,978.5 C21.1@1345,978.5 v1(1386.5,978.5)
  Top Layer w15: v1(115,2014) U5.5@115,2049.57 ; R19.2@268.19,2050.43 v1(306.81,2050.43) ; R20.2@268.19,2160.43 v1(306.81,2160.43)
  Top Layer w20: J10.1@1565,326.42 v1(1565,459)
+3V3LP: J5.1 J9.1 | length 856.7
  Bottom Layer w50: J5.1@150,1300 480,1630 J9.1@480,2020
+5V: J5.2
AGND: C11.2 NT1.1 R9.1 R10.1 U2.1 U2.4 U2.5 U2.29 U2.30 U2.32 U2.33 U2.34 U2.37
  other v4: 1667.21,2406.8 1697.92,2406.8 1728.63,2406.8 1667.21,2474.52 1697.92,2474.52 1728.63,2474.52
GND: C5.2 C6.2 C7.2 C8.2 C9.2 C10.2 C12.2 C13.2 C14.2 C15.2 C16.2 C17.2 C18.2 C19.2 C20.2 C21.2 C22.2 C23.2 D14.1 D16.1 D17.2 D18.1 D19.1 J3.1 J4.5 J5.4 J6.2 J7.5 J7.6 J10.4 NT1.2 R14.1 R15.1 S2.1 S3.1 U2.8 U2.9 U2.16 U2.17 U2.18 U2.19 U2.20 U2.40 U3.4 U4.14 U4.16 U4.39 U4.49 U4.56 U4.65 U5.2 Y1.2 | length 2311.3
  Top Layer w8: R15.1@575.5,267 575.5,264 599.82,239.68 ; J4.5@599.82,187.51 599.82,239.68 ; U3.4@631.32,240.47 630.52,239.68 599.82,239.68
  Top Layer w10: v1@786,886 v1(789,883) ; v1@789.62,883.62 v1(789,883) ; C23.2@824.38,883 v1(789,883) ; C23.2@825,883.62 846.88,883.62 860.97,869.53 U4.39@885.77,869.53 ; U4.49@911.33,666.77 911.33,691.32 v1(930,710) ; U4.56@1049.15,666.77 v1(1049.15,709.16) ; U4.14@1232.23,948.27 1280.35,948.27 C20.2@1290,938.62 1296.62,932 v1(1326,932) ; U4.16@1232.23,987.64 1244.02,987.64 1297.87,1041.5 C21.2@1345,1041.5 v1(1386.5,1041.5) ; C18.2@1300.5,1105 v1(1341.99,1105) ; U2.8@1497,2606.35 U2.8@1497.13,2606.21
  Top Layer w15: U5.2@115,2159.8 v1(115,2195.37) ; v1(1079,348) Y1.2@1079,426
  Top Layer w20: D19.1@70,1671.5 v3(70,1733) D18.1@70,1793.5 ; S3.1@137.05,1639.99 v3(137.05,1732.95) S2.1@137.05,1824.99 ; v1@498.62,343.38 R14.1@540,343.38 C15.2@581,343.38 R15.1@581,272.5 ; v1(575,2430) J7.5@575,2518.9 ; R15.1@575.5,267 R15.1@581,272.5 ; R15.1@581,269.5 R15.1@581,272.5 ; v1(625,2430) J7.6@625,2518.9 ; C14.2@704,343.38 709.24,348.62 C13.2@746,348.62 ; v1(746,390.12) C13.2@746,348.62 ; v1@815,443 v1(813,441) C12.2@813,390 811.22,390 769.84,348.62 C13.2@746,348.62 ; D17.2@906.47,432 D17.2@909,429.47 v1(909,470.96) ; v1(965,505) 967.62,505 C19.2@999,536.38 C17.2@1040,536.38 ; J10.4@1715,326.42 v1(1715,459)
  Top Layer w60: D14.1@1437.48,1770 1437.48,1672.52 1580,1530 J3.1@1700,1530
  other v1: 1090,70 230,140 1810,160 910,200 1360,200 1140,250 110,270 1260,340 498,344 1440,390 1460,570 1400,680 670,1020 770,1130 440,1160 520,1250 400,1350 1270,1390 1510,1420 1050,1430 2030,1520 1200,1530 960,1620 1920,1630 770,1720 290,2400 60,2550 200,2550 290,2710
  other v2: 985.18,766.18 1059,766.18 1132.82,766.18 1059,803.09 985.18,840 1022.09,840 1059,840 1095.91,840 1132.82,840 1059,876.91 985.18,913.82 1059,913.82 1132.82,913.82
  other v3: 1350,2215 1385,2215 1420,2215 1315,2260 1315,2295 1315,2330 1495,2405 1495,2435 1495,2465 1495,2495 1495,2525 1495,2555
GPIO1: J5.9 U4.2 | length 1203.2
  Top Layer w8: v1(1198,712) v1(1198,712) U4.2@1232.23,712.05
  Bottom Layer w15: J5.9@150,900 200,850 320,850 510,660 825,660 844,679 1165,679 v1(1198,712)
GPIO2: J5.11 U4.1 | length 1278.9
  Top Layer w8: U4.1@1232.23,692.36 1257.64,692.36 v1(1270,680)
  Bottom Layer w15: J5.11@150,800 200,750 320,750 470,600 825,600 870,645 1235,645 v1(1270,680)
GPIO3: J5.15 U4.3 | length 1359
  Top Layer w8: U4.3@1232.23,731.73 1286.27,731.73 v1(1303,715)
  Bottom Layer w15: J5.15@150,600 202.15,547.85 842.85,547.85 905,610 1262,610 1303,651 v1(1303,715)
GPIO4: J6.8 U4.7 | length 946.1
  Top Layer w8: U4.7@1232.23,810.47 1247,810.47 1276.53,840
  Top Layer w15: 1276.53,840 1287.53,851 1979,851 2005,877 2005,945 J6.8@1950,1000
GPIO5: J6.16 U4.6 | length 818.5
  Top Layer w8: U4.6@1232.23,790.79 1262.79,790.79 1289,817 1307,817
  Top Layer w15: 1307,817 1636,817 1803,650 1900,650 J6.16@1950,600
GPIO6: J6.18 U4.5 | length 840.8
  Top Layer w8: U4.5@1232.23,771.1 1273.1,771.1 1286,784 1306,784
  Top Layer w15: 1306,784 1565,784 1799,550 1900,550 J6.18@1950,500
GPIO7: J6.20 U4.4 | length 863.3
  Top Layer w8: U4.4@1232.23,751.42 1311,751.42
  Top Layer w15: 1311,751.42 1495.58,751.42 1797,450 1900,450 J6.20@1950,400
MSP_DM: C14.1 R13.2 U4.52 | length 486.1
  Top Layer w8: 859,559 885,559 970.39,644.39 U4.52@970.39,666.77
  Top Layer w20: R13.2@663,390.62 C14.1@704,390.62 704,478 785,559 859,559
MSP_DP: C15.1 R8.1 R11.2 R14.2 U4.50 | length 715.7
  Top Layer w8: 859,634 910.98,634 931.02,654.03 U4.50@931.02,666.77
  Top Layer w20: R14.2@540,390.62 R14.2@541,390.62 ; R8.1@622,441.38 R11.2@622,390.62 C15.1@581,390.62 R14.2@541,390.62 ; 859,634 663,634 541,512 R14.2@541,390.62
MSP_PUR: R4.2 R8.2 U4.51 | length 465.3
  Top Layer w8: 858,596 898,596 950.7,648.7 U4.51@950.7,666.77
  Top Layer w20: R4.2@571.62,489.62 R8.2@621,489.62 ; R8.2@620.62,485 731.62,596 858,596
NetC6_1: C6.1 C7.1 D13.1 R5.2 U2.26
NetC11_1: C11.1 U2.28 | length 59.1
  Top Layer w15: U2.28@1709.73,2257.79 1709.73,2220.27 C11.1@1725,2205
NetC16_1: C16.1 J10.2 R21.1 U4.64 | length 694.6
  Top Layer w8: U4.64@1206.67,666.77 1206.67,641.68 1221,627.35
  Top Layer w20: 1221,627.35 1343.35,505 1574,505 1615,464 R21.1@1615,423.62 ; J10.2@1615,326.42 R21.1@1615,423.62 ; C16.1@1665,423.62 R21.1@1615,423.62
NetC17_1: C17.1 U4.55 | length 86.1
  Top Layer w8: U4.55@1029.46,666.77 1029.46,620.53 1039,611 C17.1@1039,584.62
NetC18_1: C18.1 U4.17 | length 104.5
  Top Layer w8: U4.17@1206.67,1013.23 1206.67,1074.17 C18.1@1237.5,1105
